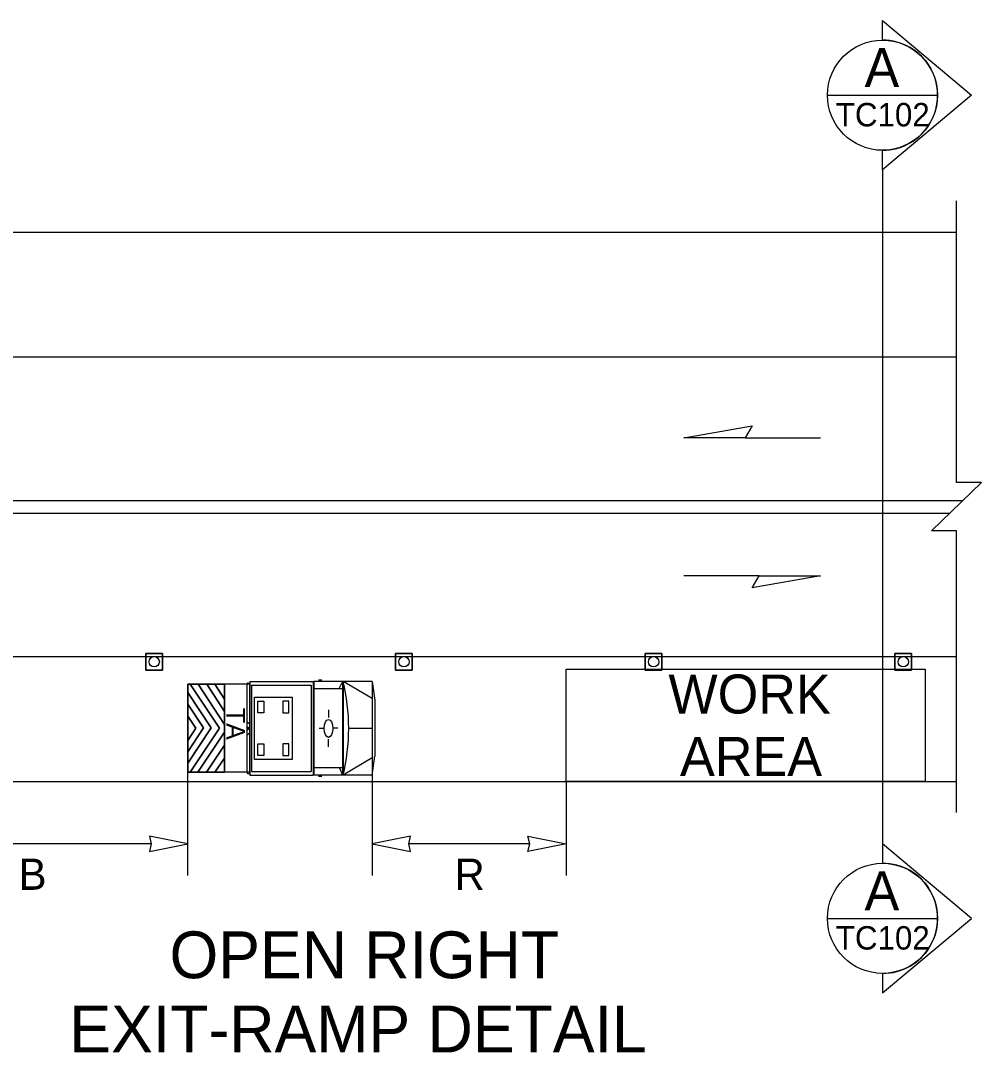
# Model space of a CAD drawing. Extents: x 99999.1 to 100055.7, y 99995 to 100013.2.
# Drawn here: x 100025.157 to 100027.619, y 100006.096 to 100008.741 of the extents above; entities that cross this region are included whole.
import ezdxf

# ---------------------------------------------------------------- set-up
doc = ezdxf.new("R2010")
doc.units = 0
for name, color, linetype in [('RD_MK_LineDblYellowCenter', 7, 'Continuous'), ('RD_MK_LineEdgeWhite', 7, 'Continuous'), ('RD_MK_LineEdgeYellow', 7, 'Continuous'), ('SH_DE_DetailHeading2Text', 7, 'Continuous'), ('SH_TI_WZSectionCut', 7, 'Continuous'), ('TR_WZ_TrafficCone', 7, 'Continuous'), ('TR_WZ_TransportableAttenuator', 7, 'Continuous'), ('TR_WZ_WorkAreaLabel', 7, 'Continuous'), ('TR_WZ_WorkZoneDetails', 7, 'Continuous'), ('TR_WZ_WorkZoneTextCurrent', 7, 'Continuous')]:
    doc.layers.add(name, color=color, linetype=linetype)

msp = doc.modelspace()

# ---------------------------------------------------------------- linework, layer by layer
at = {"layer": 'RD_MK_LineDblYellowCenter'}
for p, q in [((100020.3365, 100007.5109), (100027.5715, 100007.5109)), ((100020.3035, 100007.4789), (100027.5385, 100007.4789))]:
    msp.add_line(p, q, dxfattribs=at)
at = {"layer": 'RD_MK_LineEdgeWhite'}
msp.add_line((100020.32, 100007.8789), (100027.555, 100007.8789), dxfattribs=at)
at = {"layer": 'RD_MK_LineEdgeYellow'}
msp.add_line((100024.0968, 100007.1109), (100027.555, 100007.1109), dxfattribs=at)
at = {"layer": 'SH_TI_WZSectionCut'}
for p, q in [((100027.3657, 100008.6913), (100027.3657, 100008.7412)), ((100027.3657, 100008.7412), (100027.5938, 100008.55)), ((100027.5938, 100008.55), (100027.3657, 100008.3589)), ((100027.3657, 100008.3589), (100027.3657, 100008.4088)), ((100027.3657, 100008.3589), (100027.3657, 100006.6309)), ((100027.3657, 100006.6309), (100027.3657, 100006.581)), ((100027.5939, 100006.4398), (100027.3657, 100006.6309)), ((100027.3657, 100006.2486), (100027.5939, 100006.4398)), ((100027.3657, 100006.2985), (100027.3657, 100006.2486))]:
    msp.add_line(p, q, dxfattribs=at)
for points in [[(100027.2245, 100008.5501), (100027.5069, 100008.5501)], [(100027.2245, 100006.4398), (100027.5069, 100006.4398)]]:
    msp.add_lwpolyline(points, dxfattribs=at)
for centre in [(100027.3657, 100008.55), (100027.3657, 100006.4398)]:
    msp.add_circle(centre, 0.1412, dxfattribs=at)
for centre in [(100027.3657, 100008.55), (100027.3657, 100006.4398)]:
    msp.add_arc(centre, 0.1412, 269.9978, 90.0022, dxfattribs=at)
at = {"layer": 'TR_WZ_TrafficCone'}
for points in [[(100025.4776, 100007.1189), (100025.5203, 100007.1189), (100025.5203, 100007.0762), (100025.4776, 100007.0762), (100025.4776, 100007.1189)], [(100025.4776, 100007.0762), (100025.5203, 100007.0762), (100025.5203, 100007.1189), (100025.4776, 100007.1189), (100025.4776, 100007.0762)], [(100026.1176, 100007.1189), (100026.1603, 100007.1189), (100026.1603, 100007.0762), (100026.1176, 100007.0762), (100026.1176, 100007.1189)], [(100026.1176, 100007.0762), (100026.1603, 100007.0762), (100026.1603, 100007.1189), (100026.1176, 100007.1189), (100026.1176, 100007.0762)], [(100026.7576, 100007.1189), (100026.8003, 100007.1189), (100026.8003, 100007.0762), (100026.7576, 100007.0762), (100026.7576, 100007.1189)], [(100026.7576, 100007.0762), (100026.8003, 100007.0762), (100026.8003, 100007.1189), (100026.7576, 100007.1189), (100026.7576, 100007.0762)], [(100027.3976, 100007.1189), (100027.4403, 100007.1189), (100027.4403, 100007.0762), (100027.3976, 100007.0762), (100027.3976, 100007.1189)], [(100027.3976, 100007.0762), (100027.4403, 100007.0762), (100027.4403, 100007.1189), (100027.3976, 100007.1189), (100027.3976, 100007.0762)]]:
    msp.add_lwpolyline(points, dxfattribs=at)
for centre in [(100025.4989, 100007.0976), (100026.1389, 100007.0976), (100026.7789, 100007.0976), (100027.4189, 100007.0976)]:
    msp.add_circle(centre, 0.0133, dxfattribs=at)
at = {"layer": 'TR_WZ_TransportableAttenuator'}
for p, q in [((100025.6659, 100006.9271), (100025.591, 100007.0398)), ((100025.591, 100007.0398), (100025.6114, 100007.0398)), ((100025.591, 100007.0398), (100025.6659, 100006.9271)), ((100025.6114, 100007.0398), (100025.591, 100007.0398)), ((100025.6114, 100007.0398), (100025.6792, 100006.9371)), ((100025.6792, 100006.9371), (100025.6114, 100007.0398)), ((100025.6792, 100006.9703), (100025.6336, 100007.0398)), ((100025.6336, 100007.0398), (100025.6539, 100007.0398)), ((100025.6539, 100007.0398), (100025.6336, 100007.0398)), ((100025.6336, 100007.0398), (100025.6792, 100006.9703)), ((100025.6539, 100007.0398), (100025.6792, 100007.0016)), ((100025.6792, 100007.0016), (100025.6539, 100007.0398)), ((100025.6792, 100006.8145), (100025.6792, 100007.0398)), ((100025.7436, 100007.0398), (100025.6792, 100007.0398)), ((100025.7359, 100007.0357), (100025.7359, 100006.8182)), ((100025.7395, 100007.043), (100025.743, 100007.043)), ((100025.743, 100007.043), (100025.743, 100006.8108)), ((100025.7436, 100007.0469), (100025.9061, 100007.0469)), ((100025.7436, 100007.0469), (100025.7436, 100006.8069)), ((100025.7436, 100007.0394), (100025.7436, 100006.8145)), ((100025.7482, 100007.0374), (100025.7482, 100006.8165)), ((100025.7482, 100007.0374), (100025.9015, 100007.0374)), ((100025.9015, 100007.0374), (100025.9015, 100006.8165)), ((100025.9061, 100007.0469), (100025.9061, 100006.8069)), ((100025.9083, 100007.0469), (100025.9083, 100006.8069)), ((100026.0575, 100007.0469), (100025.9083, 100007.0469)), ((100025.9286, 100007.0503), (100025.9196, 100007.0503)), ((100025.9815, 100007.0469), (100025.972, 100007.0283)), ((100025.9815, 100007.0469), (100025.9815, 100006.8069)), ((100025.9829, 100007.0469), (100025.9829, 100006.8069)), ((100026.0575, 100007.003), (100025.9829, 100007.0469)), ((100026.0575, 100007.0469), (100026.0575, 100006.8069)), ((100026.0575, 100007.0469), (100026.0648, 100006.9985)), ((100025.5848, 100007.0184), (100025.6449, 100006.9278)), ((100025.5848, 100006.9892), (100025.5848, 100007.0184)), ((100025.6449, 100006.9278), (100025.5848, 100007.0184)), ((100025.5848, 100007.0184), (100025.5848, 100006.9892)), ((100025.9815, 100007.0283), (100025.9083, 100007.0283)), ((100025.6256, 100006.9281), (100025.5848, 100006.9892)), ((100025.5848, 100006.9892), (100025.6256, 100006.9281)), ((100025.6792, 100007.0016), (100025.6792, 100006.9703)), ((100025.6792, 100006.9703), (100025.6792, 100007.0016)), ((100026.0648, 100006.9985), (100026.0648, 100006.8554)), ((100025.5848, 100006.9583), (100025.6057, 100006.9273)), ((100025.5848, 100006.8959), (100025.5848, 100006.9583)), ((100025.6057, 100006.9273), (100025.5848, 100006.9583)), ((100025.5848, 100006.9583), (100025.5848, 100006.8959)), ((100025.9457, 100006.9745), (100025.9457, 100006.9551)), ((100025.5848, 100006.8667), (100025.6256, 100006.9281)), ((100025.6256, 100006.9281), (100025.5848, 100006.8667)), ((100025.6449, 100006.9278), (100025.5848, 100006.8373)), ((100025.5848, 100006.8373), (100025.6449, 100006.9278)), ((100025.6792, 100006.9371), (100025.6792, 100006.917)), ((100025.6792, 100006.917), (100025.6792, 100006.9371)), ((100025.7359, 100006.9438), (100025.743, 100006.9393)), ((100025.7395, 100006.9303), (100025.7395, 100006.9235)), ((100025.6057, 100006.9273), (100025.5848, 100006.8959)), ((100025.5848, 100006.8959), (100025.6057, 100006.9273)), ((100025.591, 100006.8144), (100025.6659, 100006.9271)), ((100025.6659, 100006.9271), (100025.591, 100006.8144)), ((100025.6792, 100006.917), (100025.611, 100006.8144)), ((100025.611, 100006.8144), (100025.6792, 100006.917)), ((100025.7359, 100006.91), (100025.743, 100006.9145)), ((100025.7378, 100006.9269), (100025.7411, 100006.9269)), ((100025.9219, 100006.9271), (100025.9318, 100006.927)), ((100025.9346, 100006.9265), (100025.9346, 100006.9265)), ((100025.9695, 100006.9271), (100025.9596, 100006.927)), ((100026.0575, 100006.9269), (100025.9975, 100006.9269)), ((100025.633, 100006.8144), (100025.6792, 100006.8838)), ((100025.6792, 100006.8838), (100025.633, 100006.8144)), ((100025.6792, 100006.8838), (100025.6792, 100006.8507)), ((100025.6792, 100006.8507), (100025.6792, 100006.8838)), ((100025.9457, 100006.8794), (100025.9457, 100006.8988)), ((100025.5848, 100006.8373), (100025.5848, 100006.8667)), ((100025.5848, 100006.8667), (100025.5848, 100006.8373)), ((100025.6792, 100006.8507), (100025.6546, 100006.8144)), ((100025.6546, 100006.8144), (100025.6792, 100006.8507)), ((100026.0575, 100006.8509), (100025.9829, 100006.8069)), ((100026.0575, 100006.8069), (100026.0648, 100006.8554)), ((100025.9815, 100006.8255), (100025.9083, 100006.8255)), ((100025.9737, 100006.8255), (100025.9815, 100006.8069)), ((100025.611, 100006.8144), (100025.591, 100006.8144)), ((100025.591, 100006.8144), (100025.611, 100006.8144)), ((100025.6546, 100006.8144), (100025.633, 100006.8144)), ((100025.633, 100006.8144), (100025.6546, 100006.8144)), ((100025.7436, 100006.8145), (100025.6792, 100006.8145)), ((100025.7395, 100006.8108), (100025.743, 100006.8108)), ((100025.7436, 100006.8069), (100025.9061, 100006.8069)), ((100025.7482, 100006.8165), (100025.9015, 100006.8165)), ((100026.0575, 100006.8069), (100025.9083, 100006.8069)), ((100025.9286, 100006.8036), (100025.9196, 100006.8036))]:
    msp.add_line(p, q, dxfattribs=at)
for points in [[(100025.6792, 100006.8144), (100025.5848, 100006.8144), (100025.5848, 100007.0398), (100025.6792, 100007.0398)], [(100025.7562, 100007.0069), (100025.8522, 100007.0069), (100025.8522, 100006.8469), (100025.7562, 100006.8469)], [(100025.7642, 100006.9969), (100025.7802, 100006.9969), (100025.7802, 100006.9669), (100025.7642, 100006.9669)], [(100025.8442, 100006.9969), (100025.8282, 100006.9969), (100025.8282, 100006.9669), (100025.8442, 100006.9669)], [(100025.7642, 100006.8869), (100025.7802, 100006.8869), (100025.7802, 100006.8569), (100025.7642, 100006.8569)], [(100025.8442, 100006.8869), (100025.8282, 100006.8869), (100025.8282, 100006.8569), (100025.8442, 100006.8569)]]:
    msp.add_lwpolyline(points, close=True, dxfattribs=at)
msp.add_lwpolyline([(100025.6792, 100007.0398), (100025.5848, 100007.0398), (100025.5848, 100006.8144), (100025.6792, 100006.8145)], dxfattribs=at)
for centre, major_axis, start_param, end_param in [((100025.7395, 100007.0357), (0, 0.00732), 6.283185, 7.853982), ((100025.8762, 100006.9269), (0, 0.2519), 4.215852, 5.209111), ((100025.7395, 100006.8182), (0, -0.00732), 4.712389, 6.283185)]:
    msp.add_ellipse(centre, major_axis=major_axis, ratio=0.481608, start_param=start_param, end_param=end_param, dxfattribs=at)
for centre, major_axis in [((100025.7395, 100006.9269), (0, -0.00338)), ((100025.9457, 100006.9269), (0, -0.0231))]:
    msp.add_ellipse(centre, major_axis=major_axis, ratio=0.481608, dxfattribs=at)
at = {"layer": 'TR_WZ_WorkZoneDetails'}
for p, q in [((100020.32, 100008.1989), (100027.555, 100008.1989)), ((100027.0136, 100007.6715), (100027.2065, 100007.6715)), ((100027.0492, 100007.3183), (100026.8563, 100007.3183)), ((100027.0492, 100007.3183), (100026.8563, 100007.3183)), ((100025.5848, 100006.5495), (100025.5848, 100006.8144)), ((100026.0575, 100006.8069), (100026.0575, 100006.5495)), ((100024.0968, 100006.7909), (100027.555, 100006.7909)), ((100026.5552, 100006.7909), (100026.5552, 100006.5495)), ((100025.4911, 100006.6309), (100024.8785, 100006.6309)), ((100026.4615, 100006.6309), (100026.1512, 100006.6309))]:
    msp.add_line(p, q, dxfattribs=at)
msp.add_lwpolyline([(100027.555, 100006.7109), (100027.555, 100007.433), (100027.491, 100007.433), (100027.619, 100007.5569), (100027.555, 100007.5569), (100027.555, 100008.2789)], dxfattribs=at)
for points in [[(100026.8563, 100007.6715), (100027.0314, 100007.7023), (100027.0136, 100007.6715)], [(100027.2065, 100007.3183), (100027.0314, 100007.2875), (100027.0492, 100007.3183)], [(100027.2065, 100007.3183), (100027.0314, 100007.2875), (100027.0492, 100007.3183)], [(100026.5552, 100006.7909), (100026.5552, 100007.0789), (100027.475, 100007.0789), (100027.475, 100006.7909)], [(100025.5848, 100006.6309), (100025.4865, 100006.6502), (100025.4911, 100006.6309), (100025.4865, 100006.6116)], [(100026.0575, 100006.6309), (100026.1558, 100006.6116), (100026.1512, 100006.6309), (100026.1558, 100006.6502)], [(100026.5552, 100006.6309), (100026.4569, 100006.6116), (100026.4615, 100006.6309), (100026.4569, 100006.6502)]]:
    msp.add_lwpolyline(points, close=True, dxfattribs=at)

# ---------------------------------------------------------------- texts
at = {"layer": 'SH_DE_DetailHeading2Text'}
for s, p in [('OPEN RIGHT', (100025.5382, 100006.2863)), ('EXIT-RAMP DETAIL', (100025.2814, 100006.0963))]:
    msp.add_text(s, height=0.12, rotation=360, dxfattribs=at).set_placement(p)
at = {"layer": 'SH_TI_WZSectionCut'}
for s, height, rotation, p in [('A', 0.1, 0.01, (100027.3195, 100008.5707)), ('TC102', 0.06, 360, (100027.2459, 100008.4701)), ('A', 0.1, 0.01, (100027.3195, 100006.4604)), ('TC102', 0.06, 360, (100027.2459, 100006.3598))]:
    msp.add_text(s, height=height, rotation=rotation, dxfattribs=at).set_placement(p)
at = {"layer": 'TR_WZ_TransportableAttenuator'}
msp.add_text('TA', height=0.048, rotation=270, dxfattribs=at).set_placement((100025.6836, 100006.9796))
at = {"layer": 'TR_WZ_WorkAreaLabel'}
for s, p in [('WORK', (100026.8169, 100006.9649)), ('AREA', (100026.8465, 100006.8049))]:
    msp.add_text(s, height=0.1, dxfattribs=at).set_placement(p)
at = {"layer": 'TR_WZ_WorkZoneTextCurrent'}
for s, p in [('B', (100025.1516, 100006.5129)), ('R', (100026.2688, 100006.5129))]:
    msp.add_text(s, height=0.08, dxfattribs=at).set_placement(p)

doc.saveas('drawing.dxf')
